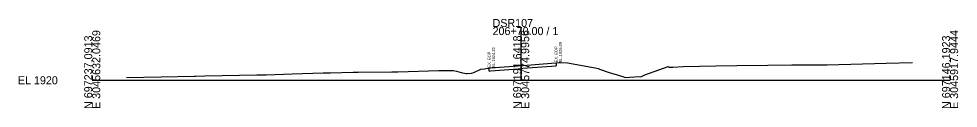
# Model space of a CAD drawing. Extents: x -26 to 19003, y -31 to 24541.
# Drawn here: x 1974.3 to 2302.8, y 14490.3 to 14521.4 of the extents above; entities that cross this region are included whole.
import ezdxf

# ---------------------------------------------------------------- set-up
doc = ezdxf.new("R2010")
doc.units = 0
for name, color, linetype in [('DESIGN - SHEET - Light Grid', 7, 'Continuous'), ('SURVEY - GROUND - Existing Pavement Layer', 7, 'Continuous'), ('SURVEY - GROUND - Existing Pavement Text', 7, 'Continuous'), ('SURVEY - GROUND - Top of Ground', 7, 'Continuous')]:
    doc.layers.add(name, color=color, linetype=linetype)

msp = doc.modelspace()

# ---------------------------------------------------------------- linework, layer by layer
at = {"layer": 'DESIGN - SHEET - Light Grid'}
for p, q in [((2150, 14500), (2150, 14518.55)), ((2000, 14500), (2150, 14500)), ((2150, 14500), (2300, 14500))]:
    msp.add_line(p, q, dxfattribs=at)
at = {"layer": 'SURVEY - GROUND - Existing Pavement Layer'}
for p, q in [((2150.61, 14504.17), (2160.66, 14504.97)), ((2160.66, 14504.97), (2162.23, 14505.09)), ((2162.23, 14506.09), (2162.23, 14505.09)), ((2138.82, 14503.23), (2138.82, 14504.23)), ((2138.82, 14503.23), (2139.28, 14503.29)), ((2139.28, 14503.29), (2148.81, 14504.02)), ((2148.81, 14504.02), (2150, 14504.12)), ((2150, 14504.12), (2150.61, 14504.17))]:
    msp.add_line(p, q, dxfattribs=at)
at = {"layer": 'SURVEY - GROUND - Top of Ground'}
msp.add_lwpolyline([(2011.93, 14500.93), (2024.14, 14501.18), (2035.66, 14501.43), (2036.13, 14501.45), (2039.34, 14501.5), (2057.56, 14501.88), (2060.8, 14501.94), (2069.86, 14502.2), (2080.75, 14502.58), (2083.34, 14502.61), (2091.29, 14502.79), (2092.16, 14502.8), (2093.03, 14502.82), (2104.76, 14502.95), (2106.87, 14502.97), (2121.25, 14503.4), (2125.9, 14503.45), (2126.3, 14503.45), (2127.4, 14503.16), (2129.01, 14502.72), (2130.81, 14502.34), (2131.17, 14502.35), (2132.66, 14502.49), (2133.49, 14502.74), (2135.91, 14503.88), (2137.21, 14504.02), (2137.64, 14504.1), (2138.42, 14504.17), (2138.82, 14504.23), (2139.28, 14504.29), (2148.81, 14505.02), (2150, 14505.12), (2150.61, 14505.17), (2160.66, 14505.97), (2162.23, 14506.09), (2163.27, 14506.17), (2163.75, 14506.18), (2166.2, 14506.11), (2175.83, 14504.35), (2176.92, 14504.16), (2177.44, 14503.92), (2181.1, 14502.65), (2182.36, 14502.3), (2185.09, 14501.48), (2186.48, 14501.03), (2191.2, 14501.29), (2191.89, 14501.25), (2193.27, 14501.92), (2201.42, 14504.84), (2201.8, 14504.62), (2203.06, 14504.61), (2206.62, 14504.82), (2218.05, 14505.05), (2225.42, 14505.17), (2236.28, 14505.25), (2244.68, 14505.43), (2256.99, 14505.4), (2277.63, 14505.93), (2286.83, 14506.14)], dxfattribs=at)

# ---------------------------------------------------------------- texts
at = {"layer": 'DESIGN - SHEET - Light Grid'}
for s, p in [('DSR107', (2140, 14518.55)), ('206+70.00 / 1', (2140, 14515.75)), ('EL 1920', (1974, 14498.6))]:
    msp.add_text(s, height=2.8, dxfattribs=at).set_placement(p)
for s, p in [('N 697237.0913', (2000, 14490)), ('E 3045632.0469', (2002.8, 14490)), ('N 697191.6418', (2150, 14490)), ('E 3045774.9956', (2152.8, 14490)), ('N 697146.1923', (2300, 14490)), ('E 3045917.9444', (2302.8, 14490))]:
    msp.add_text(s, height=2.8, rotation=90, dxfattribs=at).set_placement(p)
at = {"layer": 'SURVEY - GROUND - Existing Pavement Text'}
for s, p in [('EX. EOP', (2162.73, 14506.29)), ('EL.1926.09', (2164.23, 14506.29)), ('EX. EOP', (2139.32, 14504.43)), ('EL.1924.23', (2140.82, 14504.43))]:
    msp.add_text(s, height=1, rotation=90, dxfattribs=at).set_placement(p)

doc.saveas('drawing.dxf')
